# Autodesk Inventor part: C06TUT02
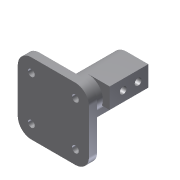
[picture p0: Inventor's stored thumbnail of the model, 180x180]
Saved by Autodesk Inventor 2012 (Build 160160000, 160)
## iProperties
Created: 2009-04
Part Number: C06TUT02
Document SubType Name: Modeling
Designer: Sham
Density: 1 g/cm^3
Material: Default
Author: Sham
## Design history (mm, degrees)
node "Sketch1"
sketch "Sketch2"
  geometry: L1 (23.49, -57.641)-(-41.51, -57.641); L2 (43.49, -37.641)-(43.49, 27.359); L3 (23.49, 47.359)-(-41.51, 47.359); L4 (-61.51, 27.359)-(-61.51, -37.641); A1 r 20 centre (23.49, -37.641) between (23.49, -57.641) and (43.49, -37.641); A2 r 20 centre (23.49, 27.359) between (43.49, 27.359) and (23.49, 47.359); A3 r 20 centre (-41.51, 27.359) between (-41.51, 47.359) and (-61.51, 27.359); A4 r 20 centre (-41.51, -37.641) between (-61.51, -37.641) and (-41.51, -57.641)
  constraints: 8 end point, 8 point on circle, 8 tangent, 4 centre point, 2 horizontal, 2 vertical
  dimensions: "d6" = 105 distance of L2.start L4.end; "d8" = 20 radius of A1; "d9" = 20 radius of A2; "d10" = 20 radius of A3; "d12" = 20 radius of A4; "d13" = 105 distance between parallel lines of L3 L1
extrude "Extrusion1" new body sketch "Sketch2" distance "d14" = 12; taper "d15" = 0 deg
hole "Hole1" diameter "d18" = 10; stored, may be unused: countersink angle "d22" = 90 deg, drill point angle "d24" = 118 deg; dims "d16" = 10, "d17" = 10, "d19" = 6, "d20" = 20, "d21" = 2, "d23" = 8
hole "Hole2" diameter "d27" = 10; stored, may be unused: countersink angle "d31" = 90 deg, drill point angle "d33" = 118 deg; dims "d25" = 10, "d26" = 10, "d28" = 6, "d29" = 20, "d30" = 2, "d32" = 8
hole "Hole3" diameter "d36" = 10; stored, may be unused: countersink angle "d40" = 90 deg, drill point angle "d42" = 118 deg; dims "d34" = 10, "d35" = 10, "d37" = 6, "d38" = 20, "d39" = 2, "d41" = 8
hole "Hole4" diameter "d45" = 10; stored, may be unused: countersink angle "d49" = 90 deg, drill point angle "d51" = 118 deg; dims "d43" = 10, "d44" = 10, "d46" = 6, "d47" = 20, "d48" = 2, "d50" = 8
sketch "Sketch3"
  geometry: L1 (-43.49, -27.359)-(-43.49, 37.641) reference; L2 (41.51, -47.359)-(-23.49, -47.359) reference; C1 r 22 at (9.01, 5.141)
  constraints: 1 centre point
  dimensions: "d52" = 44 diameter of C1; "d53" = 52.5 distance from line of L2 C1.centre; "d54" = 52.5 distance from line of L1 C1.centre
extrude "Extrusion2" join sketch "Sketch3" distance "d55" = 96; taper "d56" = 0 deg
sketch "Sketch4"
  geometry: L1 (-15, 16.093)-(-15, 25); L2 (-15, 25)-(15, 25); L3 (15, 25)-(15, 16.093); A1 r 22 centre (0, 0) between (15, 16.093) and (-15, 16.093); 2 further points
  constraints: 6 end point, 2 point on circle, 2 vertical, 1 centre point, 1 coincident, 1 horizontal, 4 other
  dimensions: "d58" = 30 distance of L1.end L2.end; "d59" = 15 distance from line of point (0, 0) L1; "d60" = 25 distance from line of L2 point (0, 0)
extrude "Extrusion3" join sketch "Sketch4" distance "d61" = 70; taper "d62" = 0 deg
sketch "Sketch5"
  geometry: L1 (29.504, 13.141)-(41.01, 13.141); L2 (41.01, 13.141)-(41.01, -16.859); L3 (41.01, -16.859)-(9.01, -16.859); A1 r 22 centre (9.01, 5.141) between (-5.99, 21.234) and (24.01, 21.234) reference; A2 r 22 centre (9.01, 5.141) between (9.01, -16.859) and (29.504, 13.141)
  constraints: 6 end point, 4 point on circle, 1 centre point, 1 coincident, 1 horizontal, 1 parallel, 1 tangent, 1 vertical
  dimensions: "d63" = 30 distance of L1.end L2.end; "d73" = 32 distance from line of A1.centre L2
extrude "Extrusion4" join sketch "Sketch5" distance "d64" = 57; taper "d65" = 0 deg
sketch "Sketch6"
  geometry: L1 (26.01, 7.141)-(34.01, 7.141); L2 (34.01, 7.141)-(34.01, -8.859); L3 (34.01, -8.859)-(26.01, -8.859); L4 (26.01, -8.859)-(26.01, 7.141); 2 further points
  constraints: 8 end point, 2 vertical, 1 horizontal, 1 midpoint, 1 parallel
  dimensions: "d66" = 16 distance of L1.end L2.end; "d67" = 8 distance of L2.end L3.end; "d69" = 2 distance from line of L1 point (9.01, 5.141); "d70" = 25 distance from line of L2 point (9.01, 5.141)
extrude "Extrusion5" cut sketch "Sketch6" distance "d71" = 50; taper "d72" = 0 deg
hole "Hole5" diameter "d76" = 22; stored, may be unused: countersink angle "d80" = 90 deg, drill point angle "d82" = 0 deg; dims "d74" = 10, "d75" = 10, "d77" = 6, "d78" = 20, "d79" = 2, "d81" = 8
hole "Hole6" diameter "d85" = 12; stored, may be unused: countersink angle "d89" = 90 deg, drill point angle "d91" = 118 deg; dims "d83" = 15, "d84" = 20, "d86" = 6, "d87" = 20, "d88" = 2, "d90" = 8
hole "Hole7" diameter "d94" = 12; stored, may be unused: countersink angle "d98" = 90 deg, drill point angle "d100" = 118 deg; dims "d92" = 15, "d93" = 50, "d95" = 6, "d96" = 20, "d97" = 2, "d99" = 8
hole "Hole8" diameter "d103" = 10; stored, may be unused: countersink angle "d107" = 90 deg, drill point angle "d109" = 118 deg; dims "d101" = 15, "d102" = 15, "d104" = 6, "d105" = 20, "d106" = 2, "d108" = 8
hole "Hole9" diameter "d112" = 10; stored, may be unused: countersink angle "d116" = 90 deg, drill point angle "d118" = 118 deg; dims "d110" = 15, "d111" = 37, "d113" = 6, "d114" = 20, "d115" = 2, "d117" = 8
fillet "Fillet1" dims "d119" = 5
body "Solid1"
